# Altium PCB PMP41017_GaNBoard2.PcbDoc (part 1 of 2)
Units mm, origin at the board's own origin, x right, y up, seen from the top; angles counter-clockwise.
Board outline 21.1 x 35.1 mm, 4 copper layers (Top Layer, Layer 1, Layer 2, Bottom Layer), stack 1.926 mm thick; 28 components, 38 nets, 164 pads, 603 vias.
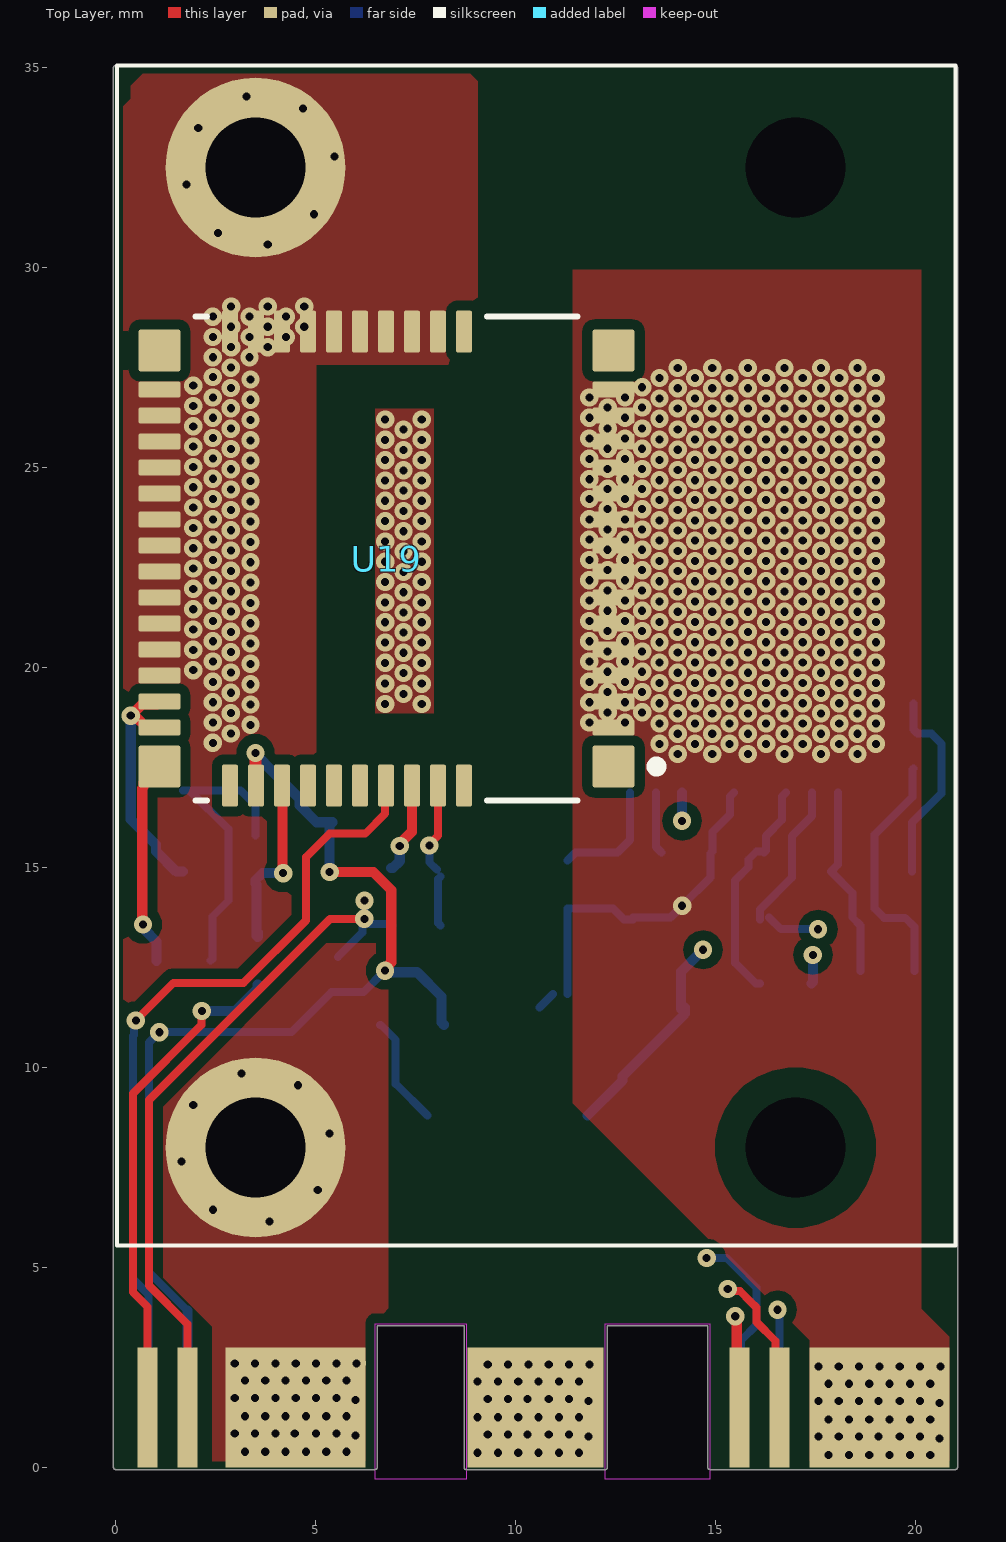
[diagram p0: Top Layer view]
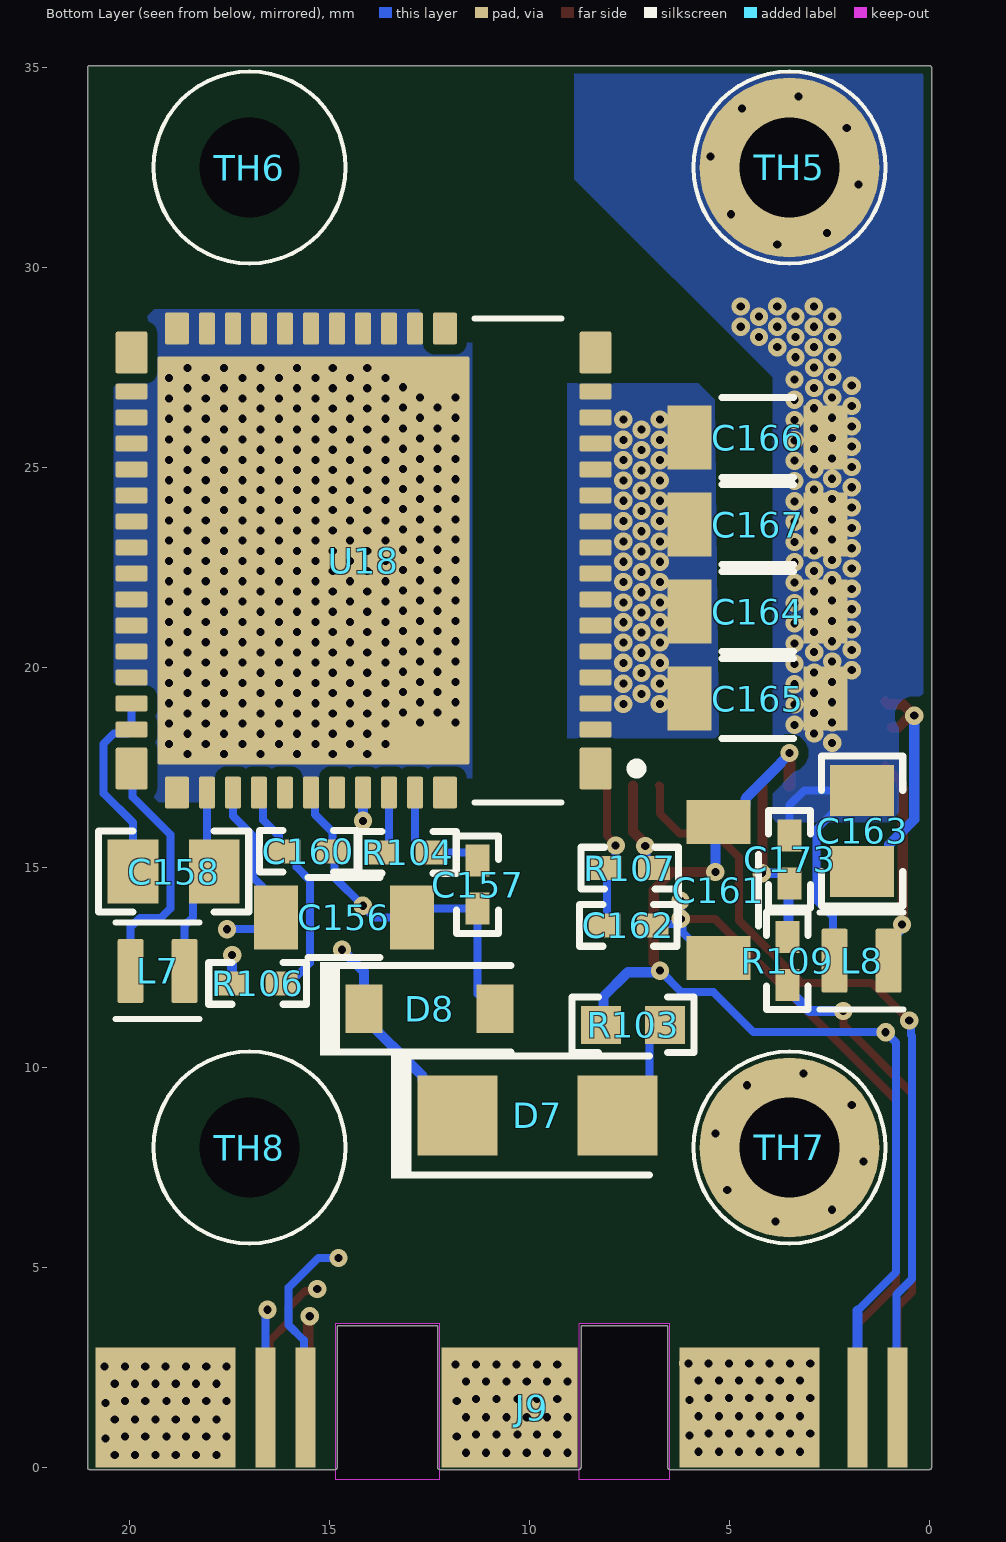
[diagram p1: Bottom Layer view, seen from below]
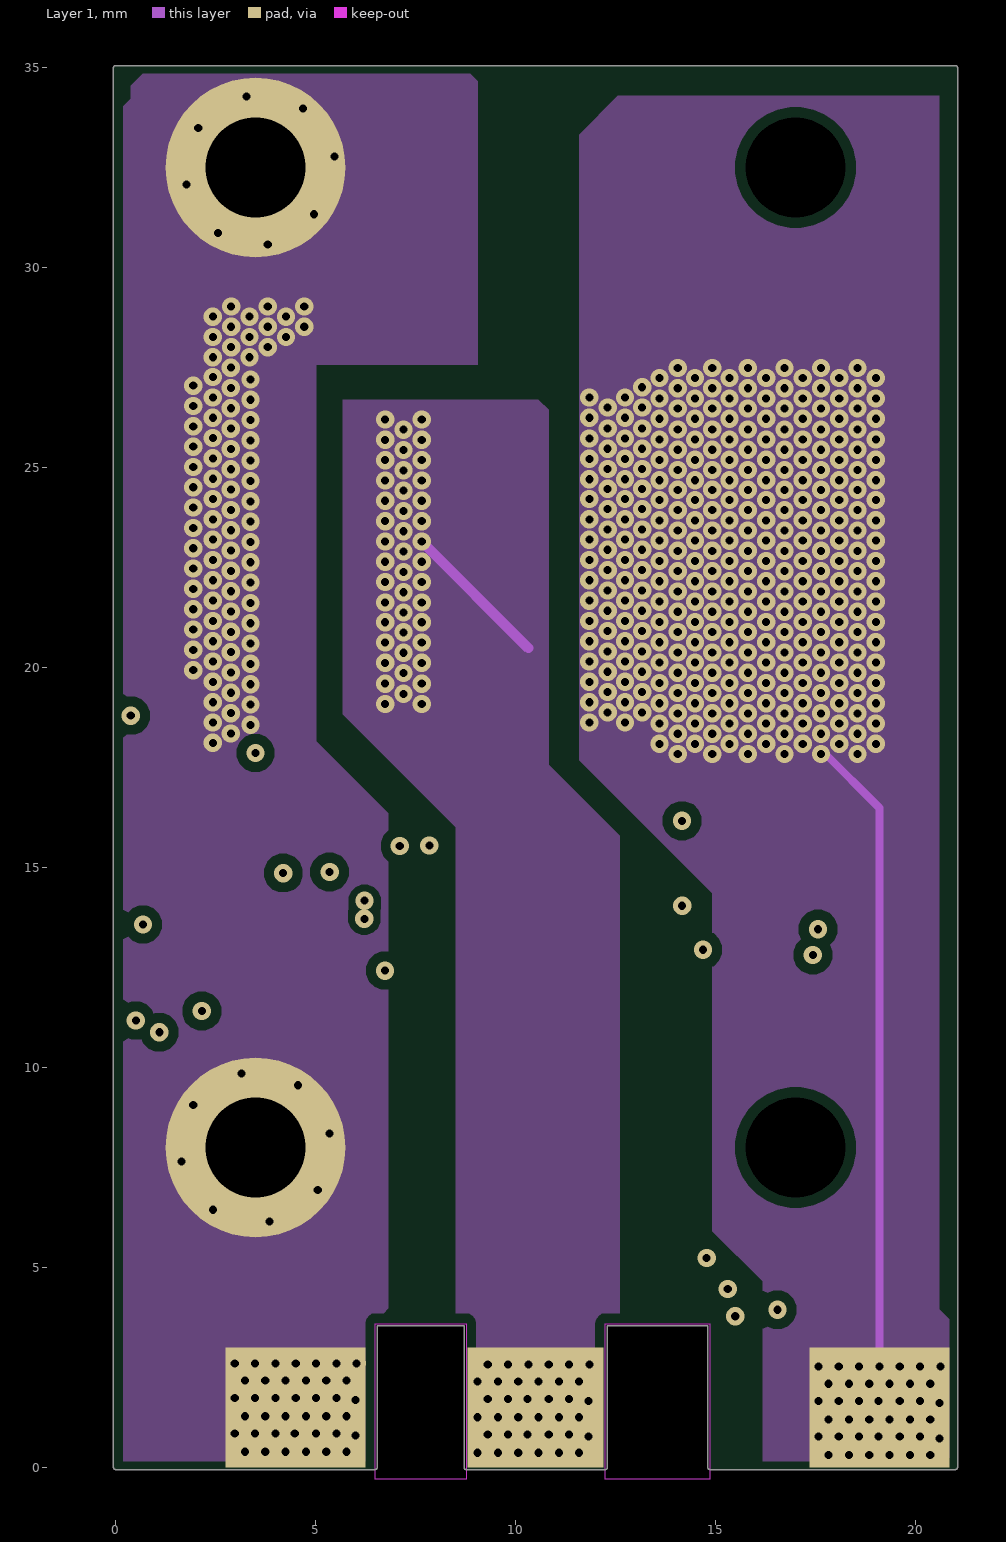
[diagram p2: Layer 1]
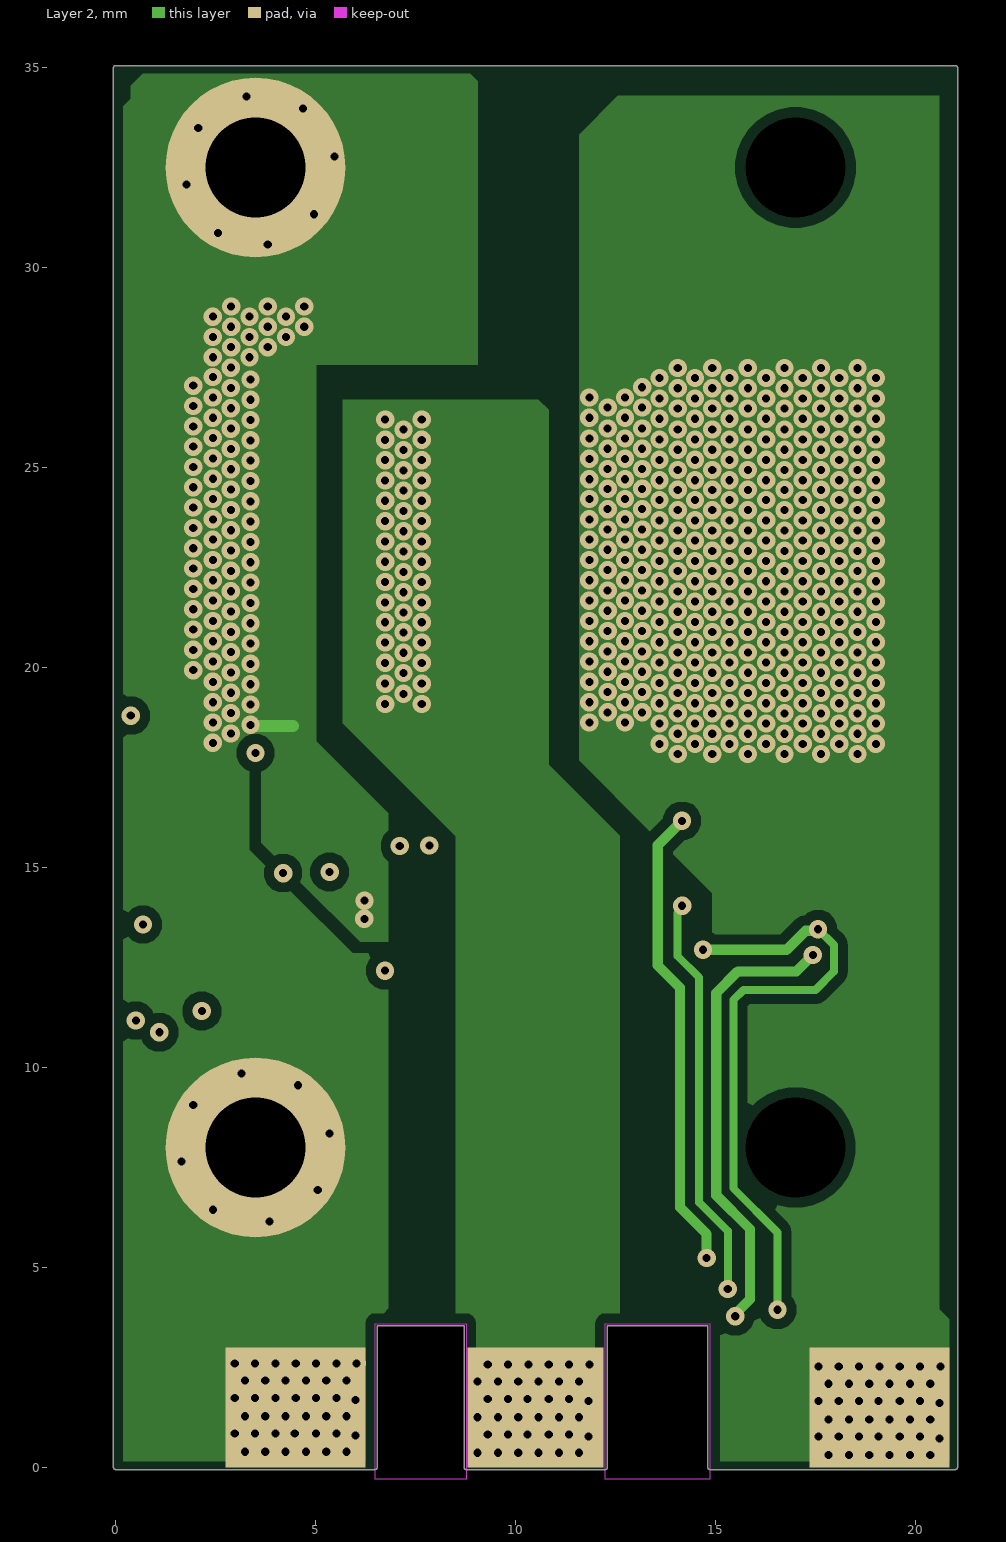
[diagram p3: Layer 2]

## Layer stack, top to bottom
Top Solder: solder mask 0.0102, Solder Resist, Dk 3.5
Top Layer: signal copper 0.07
Dielectric 1: prepreg 0.0711, PP-006, Dk 4.1
Layer 1: signal copper 0.07
Dielectric1: core 1.5037, FR-4 High Tg, Dk 4.8
Layer 2: signal copper 0.07
Dielectric 2: prepreg 0.0711, PP-006, Dk 4.1
Bottom Layer: signal copper 0.07
Bottom Solder: solder mask 0.0102, Solder Resist, Dk 3.5

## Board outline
0,-0.05 6.491,-0.05 ccw(c6.491,0) 6.541,0 6.541,3.55 8.713,3.55 8.713,0 ccw(c8.763,0) 8.763,-0.05 12.246,-0.05 ccw(c12.246,0) 12.297,0 12.297,3.55 14.809,3.55 14.809,0 ccw(c14.859,0) 14.859,-0.05 20.999,-0.05 ccw(c21,0) 21.05,0 21.05,35 ccw(c21,35) 21,35.05 0,35.05 ccw(c0,35) -0.05,35 -0.05,0 ccw(c0,0)
cut-out: 12.246,-0.294 12.246,3.6 14.859,3.6 14.859,-0.294
cut-out: 6.497,-0.294 6.497,3.6 8.763,3.6 8.763,-0.294

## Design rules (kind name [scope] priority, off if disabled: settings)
AcuteAngle [All] p1: minimum=4.50000000000000E+0001 checktracksonly=FALSE
AssemblyTestPointUsage [All] p1: valid=2
BoardOutlineClearance BoardOutlineClearance_MountingHoles [OnCopper and InComponentClass('Mounting Holes')] p1: gap=0.2 ignorepadtopadclearanceinfootprint=FALSE
BoardOutlineClearance BoardOutlineClearance_Poly [OnCopper and IsPoly] p2: gap=0.2 ignorepadtopadclearanceinfootprint=FALSE
BoardOutlineClearance [OnCopper and Not InComponentClass('Logo') and not InComponentClass('FiducialMark') and not InRegion(1000,500,4000,800) and not InPoly] p3: gap=0.2 ignorepadtopadclearanceinfootprint=FALSE
Clearance Clearance_Keepouts [((IsTrack Or IsArc) And Not InPoly) And IsFree and IsKeepOut vs ((IsTrack Or IsArc) And Not InPoly) And IsFree and IsKeepOut] p1: gap=0 ignorepadtopadclearanceinfootprint=FALSE
Clearance Clearance_Poly [InPolygon] p2: gap=0.254 ignorepadtopadclearanceinfootprint=TRUE
Clearance Clearance_FiducialMark [IsKeepOut and InComponentClass('FiducialMark') vs IsPad and InComponentClass('FiducialMark')] p3: gap=0 ignorepadtopadclearanceinfootprint=FALSE
Clearance [All] p4: gap=0.2 ignorepadtopadclearanceinfootprint=TRUE
ComponentClearance ComponentClearance_MountingHoles_FiducialMarks [InComponentClass('Mounting Holes') vs InComponentClass('FiducialMark')] p1 off: gap=1.27 collisioncheckmode=3 verticalgap=0.254 showdistances=FALSE
ComponentClearance ComponentClearance_Shunt [InComponentClass('Header') vs InComponentClass('Shunt')] p2 off: gap=0 collisioncheckmode=3 verticalgap=0 showdistances=FALSE
ComponentClearance ComponentClearance_Logo [InComponentClass('Logo')] p3 off: gap=0.762 collisioncheckmode=3 verticalgap=0.254 showdistances=FALSE
ComponentClearance ComponentClearance_ScrewToNut [(HasFootprint('NY PMS 440 0025 PH')) vs (HasFootprint('Keystone_1902C'))] p4 off: gap=0.127 collisioncheckmode=3 verticalgap=0.254 showdistances=FALSE
ComponentClearance ComponentClearance_MountingHoles [InComponentClass('Mounting Holes')] p5 off: gap=2.54 collisioncheckmode=3 verticalgap=2540 showdistances=FALSE
ComponentClearance ComponentClearance_SmallPassives [HasFootprint('0201*') or HasFootprint('0402*') or HasFootprint('0508') or HasFootprint('0603*') or HasFootprint('0612') or HasFootprint('0805*') or HasFootprint('0815*') or HasFootprint('0830*') or HasFootprint('1206*') or HasFootprint('1210*') or HasFootprint('1808*') or HasFootprint('1812*') or HasFootprint('1825*') or HasFootprint('2010*') or HasFootprint('2220*') or HasFootprint('2225*') or HasFootprint('2512*') or HasFootprint('2728*') or HasFootprint('3518*') vs HasFootprint('0201*') or HasFootprint('0402*') or HasFootprint('0508') or HasFootprint('0603*') or HasFootprint('0612') or HasFootprint('0805*') or HasFootprint('0815*') or HasFootprint('0830*') or HasFootprint('1206*') or HasFootprint('1210*') or HasFootprint('1808*') or HasFootprint('1812*') or HasFootprint('1825*') or HasFootprint('2010*') or HasFootprint('2220*') or HasFootprint('2225*') or HasFootprint('2512*') or HasFootprint('2728*') or HasFootprint('3518*')] p6 off: gap=0.38 collisioncheckmode=3 verticalgap=0.254 showdistances=FALSE
ComponentClearance ComponentClearance_THtoSMT [IsThruComponent vs IsSMTComponent] p7 off: gap=0.762 collisioncheckmode=3 verticalgap=0.762 showdistances=FALSE
ComponentClearance ComponentClearance_THtoTH [IsThruComponent vs IsThruComponent] p8 off: gap=0.508 collisioncheckmode=3 verticalgap=0.762 showdistances=FALSE
ComponentClearance [All] p9 off: gap=0.508 collisioncheckmode=3 verticalgap=0.254 showdistances=FALSE
DiffPairsRouting [All] p1: maxlimit=2.54 minlimit=0.254 mostfreqgap=0.254 toplayer_minwidth=0.381 toplayer_maxwidth=0.381 toplayer_prefwidth=0.381 midlayer1_minwidth=0.381 midlayer1_maxwidth=0.381 midlayer1_prefwidth=0.381 midlayer2_minwidth=0.381 midlayer2_maxwidth=0.381 midlayer2_prefwidth=0.381 bottomlayer_minwidth=0.381 bottomlayer_maxwidth=0.381 bottomlayer_prefwidth=0.381 maxuncoupledlength=25.4
FabricationTestPointUsage TestPointUsage [All] p1: valid=2 allowmultiple=FALSE
FabricationTestpoint Testpoint [All] p1: side=3 testpointundercomponent=TRUE minsize=1.016 maxsize=2.54 preferedsize=1.524 minholesize=0 maxholesize=1.016 preferedholesize=0.813 testpointgrid=0.025 allowsidetop=TRUE allowsidebottom=TRUE usegrid=TRUE gridtolerance=0
FanoutControl Fanout_LCC [IsLCC] p1: bgadir=Out bgaviamode=Centered fanoutstyle=Auto fanoutdirection=Alternating viagrid=0.025 // Fanout_LCC (Default Rule)
FanoutControl Fanout_BGA [IsBGA] p2: bgadir=Out bgaviamode=Centered fanoutstyle=Auto fanoutdirection=Alternating viagrid=0.025 // Fanout_BGA (Default Rule)
FanoutControl Fanout_Default [All] p4: bgadir=Out bgaviamode=Centered fanoutstyle=Auto fanoutdirection=Alternating viagrid=0.025 // Fanout_Default (Default Rule)
FanoutControl Fanout_Small [(CompPinCount < 5)] p5: bgadir=Out bgaviamode=Centered fanoutstyle=Auto fanoutdirection=OutThenIn viagrid=0.025 // Fanout_Small (Default Rule)
Height [All] p1 off: minheight=0 maxheight=30 prefheight=12.7
HoleSize [All] p1: absolutevalues=TRUE maxlimit=6.375 minlimit=0.2 maxpercent=80.000 minpercent=20.000
MinimumAnnularRing MinimumAnnularRing_ThermalPadVias [IsVia and InAnyComponent] p1: minimumring=0.12
MinimumAnnularRing [All] p2: minimumring=0.12
MinimumSolderMaskSliver MinimumSolderMaskSliver_Logo [InComponentClass('Logo') vs InComponentClass('Logo')] p1: minsoldermaskwidth=0.018
MinimumSolderMaskSliver [All] p2: minsoldermaskwidth=0.1
PlaneConnect [All] p1: planeconnectstyle=Relief reliefexpansion=0.254 reliefentries=4 reliefconductorwidth=0.254 reliefairgap=0.254
PolygonConnect [All] p1: connectstyle=Direct reliefconductorwidth=0.254 reliefentries=4 polygonreliefangle="90 Angle" airgapwidth=0.254
RoutingVias ThermalPadVias [IsVia and InAnyComponent] p1: holewidth=0.2 width=0.5 viastyle="Through Hole" minholewidth=0.2 minwidth=0.5 maxholewidth=0.33 maxwidth=0.6
RoutingVias [All] p2: holewidth=0.3 width=0.5 viastyle="Through Hole" minholewidth=0.2 minwidth=0.45 maxholewidth=1.016 maxwidth=1.651
SilkToBoardRegionClearance [Not ((IsComment or IsDesignator) And (Hide <> 'False')) and not InRegion(1000,500,4000,800)] p1:
SilkToSilkClearance SilkToSilkClearance_Pb-FreeLogo [(HasFootprint('Pb-Free_Overlay_Medium') OR HasFootprint('Pb-Free_Overlay_Small')) vs (HasFootprint('Pb-Free_Overlay_Medium') OR HasFootprint('Pb-Free_Overlay_Small'))] p1: silktosilkclearance=0
SilkToSilkClearance [All] p2: silktosilkclearance=0.1
SilkToSolderMaskClearance SilkToComponentPadClearance [(IsPad or IsFill or IsRegion) and InAnycomponent] p1: minsilkscreentomaskgap=0.127 clearancetoexposedcopper=TRUE
SilkToSolderMaskClearance "Silk to Solder Mask Opening" [All] p2: minsilkscreentomaskgap=0.1 clearancetoexposedcopper=FALSE
SolderMaskExpansion [All] p1: expansion=0.05 istentingtop=FALSE
UnRoutedNet [All] p1: checkbadconnections=TRUE
Width [All] p1: maxlimit=2.54 minlimit=0.152 preferedwidth=0.254 checkconnectedcopper=TRUE
13 further rules are at their usual default settings.

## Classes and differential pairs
net class VSWNET: 5V_H FAULT_H_1 INH ISO_12V_H NC2_1 NC4_1 NetC160_2 NetL7_2 OC_H_1 PGND RDRV_H_1 SW TEMP_H_1 U1NC17_1 U1NC28_1 U1NC54_1 U2NC1_1 U2NC16_1 VNEG_H_1
net class VHV: HVBUS U1NC1_1 U1NC16_1
net class PGND: 5V_L FAULT_L_1 INL ISO_12V_L NetC173_2 NetD7_2 NetL8_2 NetR107_1 OC_L_1 PGND TEMP_L_1 U2NC17_1 U2NC27_1 U2NC43_1 U2NC52_1 U2NC57_1 VNEG_L_1

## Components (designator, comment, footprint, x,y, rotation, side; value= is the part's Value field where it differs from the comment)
C156 "C1206C106K3RACTU" 1206_190 14.64,13.754 r180 bottom value=10uF
C157 "CL05B224KO5NNNC" 0402 11.3,14.573 r270 bottom value=0.22uF
C158 "GRM219R61E225KA12D" 0805_HV 18.9,14.9 r180 bottom value=2.2uF
C160 "C1005C0G1H220J050BA" 0402 15.529,15.405 r0 bottom value=22pF
C161 "C1206C106K3RACTU" 1206_190 5.276,14.432 r90 bottom value=10uF
C162 "CL05B224KO5NNNC" 0402 7.528,13.552 r0 bottom value=0.22uF
C163 "GRM219R61E225KA12D" 0805_HV 1.686,15.913 r90 bottom value=2.2uF
C164 "C1206C223KDRACTU" 1206_190 4.295,21.399 r180 bottom value=0.022uF
C165 "C1206C223KDRACTU" 1206_190 4.295,19.224 r180 bottom value=0.022uF
C166 "C1206C223KDRACTU" 1206_190 4.295,25.75 r180 bottom value=0.022uF
C167 "C1206C223KDRACTU" 1206_190 4.295,23.575 r180 bottom value=0.022uF
C173 "C1005C0G1H220J050BA" 0402 3.5,15.205 r270 bottom value=22pF
D7 "US1M-13-F" SMA 9.8,8.8 r180 bottom value=1000V
D8 "BZT52C16-7-F" SOD-123 12.5,11.468 r180 bottom value=16V
J9 "Edge Finger" EC_GAN_DC_HBLLC 0,4 r0 bottom locked
L7 "SDEM20161T-4R7MS" FP-SDEM20161T-4R7MS_SMD2-MFG 19.3,12.411 r0 bottom
L8 "SDEM20161T-4R7MS" FP-SDEM20161T-4R7MS_SMD2-MFG 1.7,12.671 r180 bottom
R103 "MCT06030C2008FP500" 0603 7.41,11.069 r0 bottom value=2.00
R104 "MCR01MZPJ000" 0402 13.05,15.376 r180 bottom value=0
R106 "CRCW0402300RJNED" 0402 16.799,12.103 r180 bottom value=300
R107 "MCR01MZPJ000" 0402 7.493,14.986 r0 bottom value=0
R109 "CRCW0402300RJNED" 0402 3.555,12.668 r90 bottom value=300
TH5 "M2.5 SCREW" TP_H045P075#1 3.5,31.8 r270 bottom
TH6 "M2.5 SCREW" TP_H045P075#2 17,32.5 r270 bottom
TH7 "M2.5 SCREW" TP_H045P075#3 3.5,8 r270 bottom
TH8 "M2.5 SCREW" TP_H045P075#2 17,8 r270 bottom
U18 "LMG3425R030RQZT" RQZ0054A-MFG-NV 14.15,22.675 r0 bottom
U19 "LMG3522R030Q" RQS0052A-MFG 6.775,22.725 r180 top locked

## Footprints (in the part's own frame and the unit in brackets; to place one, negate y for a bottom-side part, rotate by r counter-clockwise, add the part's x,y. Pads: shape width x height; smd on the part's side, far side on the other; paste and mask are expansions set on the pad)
0402 [mm] "0402 from SM-752 data"
  rect 0.8x0.6 smd: 1(-0.6,0) 2(0.6,0)
  silkscreen extent -1.22,-0.52 1.22,0.52, body extent -0.55,-0.3 0.55,0.3, height 0.6
0603 [mm] "0603 from SM-752 data"
  rect 1x0.95 smd: 1(-0.8,0) 2(0.8,0)
  silkscreen extent -1.52,-0.69 1.52,0.69, body extent -0.87,-0.47 0.87,0.47, height 1
0805_HV [mil] "0805 with 30mil clearance between pads"
  rect 50x63 smd: 1(-40,0) 2(40,0)
  silkscreen extent -74,-40 74,40, body extent -43,-29 43,29, height 57
1206_190 [mm] "1206_190"
  rect 1.1x1.6 smd: 1(-1.7,0) 2(1.7,0)
  silkscreen extent -0.9,-1 0.9,1, body extent -1.75,-0.95 1.75,0.95, height 1.9
EC_GAN_DC_HBLLC [mm] "Edge connector of HB LLC GaN DC"
  rect 0.5x3 smd: 1(0.8,2.5) 3(1.8,2.5) 5(15.6,2.5) 7(16.6,2.5)
  rect 0.5x3 smd far side: 2(0.8,2.5) 4(1.8,2.5) 6(15.6,2.5) 8(16.6,2.5)
  rect 3.4x3 all layers, no hole: HV(10.5,2.5)
  rect 3.5x3 all layers, no hole: PG(4.5,2.5) SW(19.1,2.5)
FP-SDEM20161T-4R7MS_SMD2-MFG [mm]
  rrect15% 0.65x1.6 smd paste+0 mask+0: 1(-0.675,0) 2(0.675,0)
  silkscreen extent -1.05,-1.22 1.05,1.2, body extent -1,-0.8 1,0.8, height 1
RQS0052A-MFG [mm]
  rrect10% 1.05x1.05 smd paste+0 mask+0: 1(-5.675,5.2) 16(-5.675,-5.2) 27(5.675,-5.2) 42(5.675,5.2)
  rrect25% 1.05x0.4 smd paste+0 mask+0: 2(-5.675,4.225) 3(-5.675,3.575) 4(-5.675,2.925) 5(-5.675,2.275) 6(-5.675,1.625) 7(-5.675,0.975) 8(-5.675,0.325) 9(-5.675,-0.325) 10(-5.675,-0.975) 11(-5.675,-1.625) 12(-5.675,-2.275) 13(-5.675,-2.925) 14(-5.675,-3.575) 15(-5.675,-4.225) 28(5.675,-4.225) 29(5.675,-3.575) 30(5.675,-2.925) 31(5.675,-2.275) 32(5.675,-1.625) 33(5.675,-0.975) 34(5.675,-0.325) 35(5.675,0.325) 36(5.675,0.975) 37(5.675,1.625) 38(5.675,2.275) 39(5.675,2.925) 40(5.675,3.575) 41(5.675,4.225)
  rrect25% 0.4x1.05 smd paste+0 mask+0: 17(-1.935,-5.675) 18(-1.285,-5.675) 19(-0.635,-5.675) 20(0.015,-5.675) 21(0.665,-5.675) 22(1.315,-5.675) 23(1.965,-5.675) 24(2.615,-5.675) 25(3.265,-5.675) 26(3.915,-5.675) 43(3.915,5.675) 44(3.265,5.675) 45(2.615,5.675) 46(1.965,5.675) 47(1.315,5.675) 48(0.665,5.675) 49(0.015,5.675) 50(-0.635,5.675) 51(-1.285,5.675) 52(-1.935,5.675)
  silkscreen extent -6.88,-6.05 4.77,6.05, body extent -6,-6 6,6, height 1
RQZ0054A-MFG-NV [mm]
  rrect13% 0.8x1.05 smd paste+0 mask+0: 1(-5.8,5.2) 16(-5.8,-5.2) 28(5.8,-5.2) 43(5.8,5.2)
  rrect25% 0.8x0.4 smd paste+0 mask+0: 2(-5.8,4.225) 3(-5.8,3.575) 4(-5.8,2.925) 5(-5.8,2.275) 6(-5.8,1.625) 7(-5.8,0.975) 8(-5.8,0.325) 9(-5.8,-0.325) 10(-5.8,-0.975) 11(-5.8,-1.625) 12(-5.8,-2.275) 13(-5.8,-2.925) 14(-5.8,-3.575) 15(-5.8,-4.225) 29(5.8,-4.225) 30(5.8,-3.575) 31(5.8,-2.925) 32(5.8,-2.275) 33(5.8,-1.625) 34(5.8,-0.975) 35(5.8,-0.325) 36(5.8,0.325) 37(5.8,0.975) 38(5.8,1.625) 39(5.8,2.275) 40(5.8,2.925) 41(5.8,3.575) 42(5.8,4.225)
  rrect17% 0.6x0.8 smd paste+0 mask+0: 17(-2.035,-5.8) 27(4.665,-5.8) 44(4.665,5.8) 54(-2.035,5.8)
  rrect25% 0.4x0.8 smd paste+0 mask+0: 18(-1.285,-5.8) 19(-0.635,-5.8) 20(0.015,-5.8) 21(0.665,-5.8) 22(1.315,-5.8) 23(1.965,-5.8) 24(2.615,-5.8) 25(3.265,-5.8) 26(3.915,-5.8) 45(3.915,5.8) 46(3.265,5.8) 47(2.615,5.8) 48(1.965,5.8) 49(1.315,5.8) 50(0.665,5.8) 51(0.015,5.8) 52(-0.635,5.8) 53(-1.285,5.8)
  rrect1% 7.8x10.2 smd paste-1000 mask+0: 55(1.25,0)
  silkscreen extent -6.95,-6.05 -2.78,6.05, body extent -6,-6 6,6, height 0.9
SMA [mm] "Molded Diode, 2-Leads, Body 4.3x2.6mm, IPC Medium Density, based on OnSemi component dimensions and land pattern"
  rect 2x2 smd: 1(-2,0) 2(2,0)
  silkscreen extent -3.66,-1.57 2.79,1.57, body extent -2.6,-1.3 2.6,1.3, height 2.42
SOD-123 [mm] "On Semi recommended land pattern"
  rect 0.915x1.22 smd: 1(-1.637,0) 2(1.637,0)
  silkscreen extent -2.74,-1.17 2.03,1.17, body extent -1.93,-0.9 1.93,0.9, height 1.35
TP_H045P075#1 [mm] "TP_H0.45P0.75"
  round 4.5 hole 2.5 unplated: 1(-0.7,0)
TP_H045P075#2 [mm] "TP_H0.45P0.75"
  round 0 hole 2.5 unplated: 1(0,0)
TP_H045P075#3 [mm] "TP_H0.45P0.75"
  round 4.5 hole 2.5 unplated: 1(0,0)

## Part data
C156 C161: library part CMP-0008589-2, "CAP, CERM, 10 uF, 25 V, +/- 10%, X7R, 1206_190", Cap_Case=1206, Manufacturer=Kemet, Supplier Part Number 1=399-7442-1-ND, TempCo=X7R, Tolerance_%=10%, Value1=Unknown, Value2=25V, ValueDisplayed=10uF
C157 C162: library part CMP-0860563-1, "CAP, CERM, 0.22 µF, 16 V,+/- 10%, X7R, 0402", Cap_Case=0402, Manufacturer="Samsung Electro-Mechanics", TempCo=X7R, Tolerance_%=10%, Value2=16V, ValueDisplayed=0.22µF
C158 C163: library part CMP-0008208-1, "CAP, CERM, 2.2 uF, 25 V, +/- 10%, X5R, 0805", Cap_Case=0805, Manufacturer=MuRata, Supplier Part Number 1=490-1701-1-ND, TempCo=X5R, Tolerance_%=10%, Value1="0.006 ohm", Value2=25V, ValueDisplayed=2.2uF
C160 C173: library part CMP-0006248-2, "CAP, CERM, 22 pF, 50 V, +/- 5%, C0G/NP0, 0402", Alternate Manufacturer=TDK, Alternate PartNumber=CGA2B2NP01H220J050BA, Cap_Case=0402, Supplier Part Number 1=445-1239-1-ND, TempCo=C0G/NP0, Tolerance_%=5%, Value1=Unknown, Value2=50V, ValueDisplayed=22pF
C164 C165 C166 C167: library part CMP-0084048-1, "CAP, CERM, 0.022 µF, 1000 V,+/- 10%, X7R, AEC-Q200 Grade 1, 1206", Cap_Case=1206, Manufacturer=Kemet, TempCo=X7R, Tolerance_%=10%, Value2=1000V, ValueDisplayed=0.022µF
D7: library part CMP-0076882-1, "Diode, Ultrafast, 1000 V, 1 A, SMA", Manufacturer="Diodes Inc.", Supplier Part Number 1=US1M-FDICT-ND, Value1=1A, Value2=1.7V
D8: library part CMP-0005769-2, "Diode, Zener, 16 V, 500 mW, AEC-Q101, SOD-123", Manufacturer="Diodes Inc.", Power_W=500mW, Supplier Part Number 1=BZT52C16-FDICT-ND, Value1=0.5W
J9: library part EC_GaN
L7 L8: library part CMP-0089347-1, "4.7µH Unshielded Inductor 1.1A 426mOhm Max 0806 (2016 Metric)", Digikey Part Number=2037-SDEM20161T-4R7MSCT-ND, Manufacturer=Cyntec, Operating Temperature Range="-55°C to +125°C", Test Frequency=1MHz, Tolerance_%=20%
R103: library part CMP-0022732-2, "RES, 2.00, 1%, 0.125 W, 0603", Manufacturer=Vishay/Beyschlag, Power_W=125mW, Supplier Part Number 1=MCT06030C2008FP500-ND, TempCo="50 ppm/C", Tolerance_%=1%, Value2=0.125W, Value_Code=2R00, ValueDisplayed=2.00
R104 R107: library part CMP-0027002-2, "RES, 0, 5%, 0.063 W, 0402", Manufacturer=Rohm, Power_W=63mW, Supplier Part Number 1=RHM0.0JCT-ND, TempCo="500 ppm/C", Tolerance_%=5%, Value2=0.063W, Value_Code=0000, ValueDisplayed=0
R106 R109: library part CMP-0026902-3, "RES, 300, 5%, 0.063 W, AEC-Q200 Grade 0, 0402", Manufacturer=Vishay-Dale, Power_W=63mW, Supplier Part Number 1=541-300JCT-ND, TempCo="200 ppm/C", Tolerance_%=5%, Value2=0.063W, Value_Code=300R, ValueDisplayed=300
TH5 TH6 TH7 TH8: library part CMP-0003719-1, "Screws, M2.5x0.45 thread, L4.0mm, Steel", Manufacturer="Keystone Electronics", PartNumber=29300, Supplier Part Number 1=534-29301
U18: library part CMP-0088545-3, "600-V 30-mΩ Integrated GaN Power Stage with Smart Driver", Manufacturer="Texas Instruments", Max Supply Voltage=18V, Min Supply Voltage=7.5V, Nominal Supply Current=13mA, Operating Temperature Range="-40°C to +125°C", Output Voltage=480V
U19: library part CMP-0089967-1, "650-V 30-mΩ GaN FET with Integrated Driver and Protection", Manufacturer="Texas Instruments", Max Supply Voltage=18V, Min Supply Voltage=7.5V, Nominal Supply Current=16mA, Operating Temperature Range="-40°C to +125°C", Output Voltage=520V

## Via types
v1: diameter 0.457, hole 0.203, Top Layer to Bottom Layer, tented both sides, 603 vias

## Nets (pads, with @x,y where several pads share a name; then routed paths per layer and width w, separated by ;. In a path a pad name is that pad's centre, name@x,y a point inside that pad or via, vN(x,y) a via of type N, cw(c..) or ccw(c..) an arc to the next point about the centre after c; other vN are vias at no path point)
5V_H: C157.1 R104.2 U18.53 | length 3
  Bottom Layer w0.2: C157.1@11.3,15.173 11.3,15.176 11.5,15.376 12.55,15.376 12.865,15.691 U18.53@12.865,16.875
5V_L: C162.2 R107.2 U19.51 | length 3.5
  Top Layer w0.2: v1(7.846,15.549) 7.846,15.581 8.06,15.795 U19.51@8.06,17.05
  Bottom Layer w0.2: v1(7.846,15.549) 7.846,15.133 R107.2@8.032,14.947 ; C162.2@8.128,13.552 8.067,13.613 8.067,14.709 R107.2@8.128,14.77
FAULT_H_1: U18.48
FAULT_L_1: U19.46
HVBUS: C164.1 C165.1 C166.1 C167.1 J9.HV U18.2 U18.3 U18.4 U18.5 U18.6 U18.7 U18.8 U18.9 U18.10 U18.11 U18.12 U18.13 U18.14 U18.15 | length 3.8
  Layer 1 w0.254: v1(7.655,23.152) 10.322,20.485
  other v1: 9.052,0.368 9.56,0.368 10.068,0.368 10.576,0.368 11.084,0.368 11.592,0.368 11.821,0.775 9.306,0.825 9.814,0.825 10.297,0.825 10.83,0.825 11.338,0.825 9.052,1.257 9.56,1.257 10.068,1.257 10.576,1.257 11.084,1.257 11.592,1.257 11.821,1.664 9.306,1.714 9.814,1.714 10.297,1.714 10.83,1.714 11.338,1.714 9.052,2.146 9.56,2.146 10.068,2.146 10.576,2.146 11.084,2.146 11.592,2.146 9.306,2.578 9.814,2.578 10.322,2.578 10.83,2.578 11.338,2.578 11.846,2.578 6.741,19.088 7.655,19.088 7.198,19.342 6.741,19.596 7.655,19.596 7.198,19.863 6.741,20.117 7.655,20.117 7.198,20.371 6.741,20.625 7.655,20.625 7.198,20.879 6.741,21.133 7.655,21.133 7.198,21.374 6.741,21.628 7.655,21.628 7.198,21.882 6.741,22.136 7.655,22.136 7.198,22.39 6.741,22.644 7.655,22.644 7.198,22.898 6.741,23.152 7.198,23.406 6.741,23.66 7.655,23.66 7.198,23.914 6.741,24.168 7.655,24.168 7.198,24.422 6.741,24.676 7.655,24.676 7.198,24.93 6.741,25.184 7.655,25.184 7.198,25.438 6.741,25.692 7.655,25.692 7.198,25.946 6.741,26.2 7.655,26.2
INH: J9.6 R106.1 | length 14.4
  Top Layer w0.254: v1(15.494,3.781) 15.533,3.743 15.533,1.567 J9.6@15.6,1.5
  Layer 2 w0.254: v1(15.494,3.781) 15.494,3.836 15.862,4.204 15.862,5.962 15.019,6.805 15.019,11.862 15.56,12.403 17.023,12.403 v1(17.434,12.814)
  Bottom Layer w0.254: R106.1@17.399,12.103 17.434,12.138 v1(17.434,12.814)
INL: J9.2 R109.1 | length 12.5
  Top Layer w0.2: J9.2@0.8,1.5 0.8,4.018 0.436,4.382 0.436,9.352 2.153,11.069 2.153,11.405 v1(2.158,11.411)
  Bottom Layer w0.254: v1(2.158,11.411) 2.997,11.411 3.555,11.968 R109.1@3.555,12.068
ISO_12V_H: C156.1 D7.1 D8.1 J9.7 U18.46 | length 28.3
  Layer 2 w0.2: v1(16.551,3.945) 16.551,5.877 15.446,6.982 15.446,11.685 15.701,11.94 17.498,11.94 17.963,12.405 17.963,13.06 v1(17.565,13.458)
  Layer 2 w0.254: v1(14.689,12.944) 16.779,12.944 17.253,13.419 17.526,13.419 v1(17.565,13.458)
  Bottom Layer w0.2: C156.1@16.11,13.7 16.11,13.95 16.915,14.755 16.915,15.79 17.415,16.29 U18.46@17.415,16.875 ; C156.1@16.34,13.754 16.636,13.458 v1(17.565,13.458) ; v1(16.551,3.945) 16.6,3.896 J9.7@16.6,1.5
  Bottom Layer w0.254: D7.1@11.8,8.8 12.673,9.673 12.673,9.783 14.238,11.347 D8.1@14.238,11.5 ; D8.1@14.137,11.468 14.138,12.393 v1(14.689,12.944)
ISO_12V_L: C161.2 J9.3 R103.2 U19.44 | length 27.2
  Top Layer w0.254: v1(5.353,14.887) 6.442,14.887 6.893,14.436 6.893,12.63 6.74,12.477 v1(6.74,12.422)
  Top Layer w0.3: v1(3.5,17.863) 3.505,17.858 3.505,17.055 U19.44@3.51,17.05 U19.44@3.512,17.052
  Bottom Layer w0.2: 1.8,3.918 0.836,4.882 0.836,10.622 v1(1.096,10.882) 4.402,10.882 5.403,11.882 6.2,11.882 v1(6.74,12.422)
  Bottom Layer w0.254: J9.3@1.8,1.5 1.8,3.918 ; v1(3.5,17.863) 3.5,17.84 3.728,17.612 3.728,17.59 4.603,16.715 4.603,16.555 5.026,16.132 C161.2@5.276,16.132 5.418,16.132 5.353,16.068 v1(5.353,14.887) ; v1(6.74,12.422) 6.779,12.383 7.542,12.383 8.149,11.776 8.149,11.129 R103.2@8.21,11.069
NC2_1: TH6.1
NC4_1: TH8.1
NetC160_2: C160.2 R106.2 U18.47 | length 5.7
  Bottom Layer w0.2: R106.2@16.108,12.099 16.008,12.099 15.49,12.618 15.49,14.678 15.829,15.017 15.829,15.205 16.029,15.405 C160.2@16.129,15.405 ; C160.2@16.215,15.376 16.262,15.423 16.262,15.79 16.665,16.193 16.665,16.775 U18.47@16.765,16.875
NetC173_2: C173.2 R109.2 U19.45 | length 4.5
  Top Layer w0.254: U19.45@4.176,17.035 4.176,14.874 v1(4.191,14.859)
  Bottom Layer w0.254: R109.2@3.555,13.368 R109.2@3.555,13.268 3.527,13.296 3.527,14.578 C173.2@3.5,14.605 3.5,14.686 3.673,14.859 v1(4.191,14.859)
NetD7_2: D7.2 R103.1 | length 2.8
  Bottom Layer w0.2: R103.1@6.61,11.069 6.631,11.069 7.006,10.694 7.006,9.594 D7.2@7.8,8.8
NetL7_2: L7.2 U18.43 | length 6.2
  Bottom Layer w0.2: U18.43@19.95,17.475 19.924,17.449 19.924,16.767 18.981,15.824 18.981,13.976 19.213,13.743 19.743,13.743 19.975,13.511 L7.2@19.975,12.411
NetL8_2: L8.2 U19.42 | length 5.2
  Top Layer w0.254: v1(0.689,13.576) 0.67,13.595 0.67,16.978 0.702,17.01 0.702,17.127 U19.42@1.1,17.525
  Bottom Layer w0.254: v1(0.689,13.576) 0.728,13.537 0.728,13.443 1.025,13.146 L8.2@1.025,12.671
NetR107_1: R107.1 U19.50 | length 2.3
  Top Layer w0.254: v1(7.108,15.536) 7.108,15.591 7.41,15.894 U19.50@7.41,17.05
  Bottom Layer w0.254: R107.1@6.893,14.986 6.935,14.986 7.108,15.159 v1(7.108,15.536)
OC_H_1: U18.50
OC_L_1: U19.48
PGND: C161.1 C162.1 C163.2 C164.2 C165.2 C166.2 C167.2 C173.1 J9.4 J9.PG L8.1 TH5.1 TH7.1 U19.18 U19.19 U19.20 U19.21 U19.22 U19.23 U19.24 U19.25 U19.26 U19.28 U19.29 U19.30 U19.31 U19.32 U19.33 U19.34 U19.35 U19.36 U19.37 U19.38 U19.39 | length 31.1
  Top Layer w0.2: J9.4@1.8,1.5 1.8,3.583 0.836,4.548 0.836,9.186 5.366,13.716 v1(6.22,13.716) ; v1@6.174,13.638 v1@6.223,13.589
  Top Layer w0.254: v1(3.806,30.572) 3.806,32.194 TH5.1@3.5,32.5 3.792,32.5 v1(4.96,31.332)
  Layer 2 w0.2: J9.PG@3.94,2.06 J9.PG@4.5,1.5
  Layer 2 w0.3: v1(3.375,18.567) 3.405,18.537 4.442,18.537
  Bottom Layer w0.2: C163.2@1.686,16.929 C163.2@1.851,16.929 ; L8.1@2.375,12.671 2.419,12.715 2.419,13.771 2.82,14.171 2.82,15.96 C163.2@1.851,16.929 ; C173.1@3.5,15.805 3.5,16.56 3.131,16.929 C163.2@1.851,16.929 ; C161.1@5.56,12.767 6.174,13.381 v1@6.174,13.54 ; v1(6.22,13.716) 6.223,13.719 6.223,14.169 v1(6.226,14.171) ; v1@6.223,13.589 6.891,13.589 C162.1@6.928,13.552
  other v1: 3.235,0.394 3.743,0.394 4.251,0.394 4.759,0.394 5.267,0.394 5.775,0.394 6.004,0.8 2.981,0.851 3.489,0.851 3.997,0.851 4.48,0.851 5.013,0.851 5.521,0.851 3.235,1.283 3.743,1.283 4.251,1.283 4.759,1.283 5.267,1.283 5.775,1.283 6.004,1.689 2.981,1.74 3.489,1.74 3.997,1.74 4.505,1.74 5.013,1.74 5.521,1.74 3.235,2.172 3.743,2.172 4.251,2.172 4.759,2.172 5.267,2.172 5.775,2.172 2.981,2.603 3.489,2.603 3.997,2.603 4.505,2.603 5.013,2.603 5.521,2.603 6.029,2.603 3.851,6.149 2.439,6.443 5.057,6.939 1.649,7.649 5.351,8.351 1.943,9.061 4.561,9.557 3.149,9.851 2.434,18.117 2.884,18.352 2.434,18.625 2.884,18.86 3.375,19.075 2.434,19.133 2.884,19.368 3.375,19.583 2.434,19.641 2.884,19.876 1.943,19.934 3.375,20.091 2.434,20.149 2.884,20.384 1.943,20.442 3.375,20.599 2.434,20.657 2.884,20.892 1.943,20.95 3.375,21.107 2.434,21.165 2.884,21.4 1.943,21.458 3.375,21.615 2.434,21.673 2.884,21.908 1.943,21.966 3.375,22.123 2.434,22.181 2.884,22.416 1.943,22.474 3.375,22.631 2.434,22.689 2.884,22.924 1.943,22.982 3.375,23.139 2.434,23.197 2.884,23.432 1.943,23.49 3.375,23.647 2.434,23.705 2.884,23.94 1.943,23.998 3.375,24.155 2.434,24.213 2.884,24.448 1.943,24.506 3.375,24.663 2.434,24.721 2.884,24.956 1.943,25.014 3.375,25.171 2.434,25.229 2.884,25.464 1.943,25.522 3.375,25.679 2.434,25.737 2.884,25.972 1.943,26.03 3.375,26.187 2.434,26.245 2.884,26.48 1.943,26.538 3.375,26.695 2.434,26.753 2.884,26.988 1.943,27.046 3.375,27.203 2.434,27.261 2.884,27.496 2.434,27.756 3.348,27.756 2.891,28.01 3.806,28.01 2.434,28.264 3.348,28.264 4.263,28.264 2.891,28.518 3.806,28.518 4.72,28.518 2.434,28.772 3.348,28.772 4.263,28.772 2.891,29.026 3.806,29.026 4.72,29.026 2.564,30.866 1.774,32.072 5.476,32.774 2.068,33.484 4.686,33.98 3.274,34.274
RDRV_H_1: R104.1 U18.52 | length 1.6
  Bottom Layer w0.2: U18.52@13.515,16.875 13.515,15.511 R104.1@13.65,15.376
